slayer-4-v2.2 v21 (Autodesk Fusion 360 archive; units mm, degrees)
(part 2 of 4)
sketch "Sketch25" plane through (0, 0, 2) normal (0, 0, 1) x axis (-1, 0, 0)
  line L1 (-27.3161, -18.7368) -> (-34.6566, -7.8543)
  line L2 (-7.8768, -19.0795) -> (-13.4582, -18.707)
  line L3 (13.4582, -18.707) -> (7.8768, -19.0795)
  line L4 (7.8768, 19.0795) -> (13.4582, 18.707)
  line L5 (-13.4582, 18.707) -> (-7.8768, 19.0795)
  line L6 (-34.6566, 7.8543) -> (-27.3161, 18.7368)
  line L7 (-34.9985, -6.7359) -> (-34.9985, 6.7359)
  line L8 (-28.5272, 6) -> (-25.1483, 6)
  line L9 (-28.4467, 11.6958) -> (-30.1852, 9.1184)
  line L10 (-29.9985, -3) -> (-23.1491, -3)
  line L11 (-31.9985, 1) -> (-31.9985, -1)
  line L12 (-23.1491, 3) -> (-29.9985, 3)
  line L13 (15.3479, -5.782) -> (13.4133, -8.1699)
  line L14 (19.6919, -8.9044) -> (18.7852, -6.3678)
  line L15 (13.4936, -15.6979) -> (15.3167, -15.5763)
  line L16 (13.4133, 8.1699) -> (15.3479, 5.782)
  line L17 (15.3167, 15.5763) -> (13.4936, 15.6979)
  line L18 (18.7852, 6.3678) -> (19.6919, 8.9044)
  line L19 (-15.3479, 5.782) -> (-13.4133, 8.1699)
  line L20 (-19.6919, 8.9044) -> (-18.7852, 6.3678)
  line L21 (-13.4936, 15.6979) -> (-15.3167, 15.5763)
  line L22 (-13.4133, -8.1699) -> (-15.3479, -5.782)
  line L23 (-15.3167, -15.5763) -> (-13.4936, -15.6979)
  line L24 (-18.7852, -6.3678) -> (-19.6919, -8.9044)
  line L25 (-30.1852, -9.1184) -> (-28.4467, -11.6958)
  line L26 (-25.1483, -6) -> (-28.5272, -6)
  line L27 (42, 0) -> (-35, 0)
  line L28 (42, -18.878) -> (42, 0)
  line L29 (-35, 0) -> (-35, -20)
  line L30 (0.0223, -24.9973) -> (-35, -20)
  line L31 (42, -18.878) -> (0.0223, -24.9973)
  arc A1 centre (-32.9985, -6.7359) radius 2 clockwise from (-34.6566, -7.8543) to (-34.9985, -6.7359)
  arc A2 centre (-24, -16.5) radius 4 clockwise from (-22.465, -20.1938) to (-27.3161, -18.7368)
  arc A3 centre (-14.7902, -38.6626) radius 20 clockwise from (-22.465, -20.1938) to (-13.4582, -18.707)
  arc A4 centre (-9.0756, -37.0396) radius 18 clockwise from (-7.8768, -19.0795) to (-1.2965, -20.8073)
  arc A5 centre (0, -18.1019) radius 3 clockwise from (1.2965, -20.8073) to (-1.2965, -20.8073)
  arc A6 centre (9.0756, -37.0396) radius 18 clockwise from (1.2965, -20.8073) to (7.8768, -19.0795)
  arc A7 centre (14.7902, -38.6626) radius 20 clockwise from (13.4582, -18.707) to (22.465, -20.1938)
  arc A8 centre (24, -16.5) radius 4 clockwise from (26.8498, -13.6931) to (22.465, -20.1938)
  arc A9 centre (41.099, 0.3411) radius 20 clockwise from (26.8498, -13.6931) to (21.1019, 0)
  arc A10 centre (41.099, -0.3411) radius 20 clockwise from (21.1019, 0) to (26.8498, 13.6931)
  arc A11 centre (24, 16.5) radius 4 clockwise from (22.465, 20.1938) to (26.8498, 13.6931)
  arc A12 centre (14.7902, 38.6626) radius 20 clockwise from (22.465, 20.1938) to (13.4582, 18.707)
  arc A13 centre (9.0756, 37.0396) radius 18 clockwise from (7.8768, 19.0795) to (1.2965, 20.8073)
  arc A14 centre (0, 18.1019) radius 3 clockwise from (-1.2965, 20.8073) to (1.2965, 20.8073)
  arc A15 centre (-9.0756, 37.0396) radius 18 clockwise from (-1.2965, 20.8073) to (-7.8768, 19.0795)
  arc A16 centre (-14.7902, 38.6626) radius 20 clockwise from (-13.4582, 18.707) to (-22.465, 20.1938)
  arc A17 centre (-24, 16.5) radius 4 clockwise from (-27.3161, 18.7368) to (-22.465, 20.1938)
  arc A18 centre (-32.9985, 6.7359) radius 2 clockwise from (-34.9985, 6.7359) to (-34.6566, 7.8543)
  arc A19 centre (-28.5272, 8) radius 2 clockwise from (-28.5272, 6) to (-30.1852, 9.1184)
  arc A20 centre (-26.7887, 10.5774) radius 2 clockwise from (-28.4467, 11.6958) to (-25.1986, 11.7906)
  arc A21 centre (-41.099, -0.3411) radius 20 clockwise from (-25.1986, 11.7906) to (-23.376, 8.9268)
  arc A22 centre (-25.1483, 8) radius 2 clockwise from (-23.376, 8.9268) to (-25.1483, 6)
  arc A23 centre (-41.099, -0.3411) radius 20 clockwise from (-21.1546, 1.149) to (-21.1019, 0)
  arc A24 centre (-41.099, 0.3411) radius 20 clockwise from (-21.1019, 0) to (-21.1546, -1.149)
  arc A25 centre (-23.1491, -1) radius 2 clockwise from (-21.1546, -1.149) to (-23.1491, -3)
  arc A26 centre (-29.9985, -1) radius 2 clockwise from (-29.9985, -3) to (-31.9985, -1)
  arc A27 centre (-29.9985, 1) radius 2 clockwise from (-31.9985, 1) to (-29.9985, 3)
  arc A28 centre (-23.1491, 1) radius 2 clockwise from (-23.1491, 3) to (-21.1546, 1.149)
  circle C1 centre (18.1019, 0) radius 1.05
  circle C2 centre (10, -10) radius 1.05
  circle C3 centre (24, -16.5) radius 1.55
  arc A29 centre (16.9019, -7.041) radius 2 clockwise from (15.3479, -5.782) to (18.7852, -6.3678)
  arc A30 centre (14.9837, -10.5874) radius 5 clockwise from (19.6919, -8.9044) to (15.3167, -15.5763)
  arc A31 centre (13.3604, -13.7024) radius 2 clockwise from (13.4936, -15.6979) to (12.0163, -12.2214)
  arc A32 centre (10, -10) radius 3 clockwise from (12.9804, -9.6573) to (12.0163, -12.2214)
  arc A33 centre (14.9673, -9.4289) radius 2 clockwise from (12.9804, -9.6573) to (13.4133, -8.1699)
  arc A34 centre (14.9673, 9.4289) radius 2 clockwise from (13.4133, 8.1699) to (12.9804, 9.6573)
  arc A35 centre (10, 10) radius 3 clockwise from (12.0163, 12.2214) to (12.9804, 9.6573)
  arc A36 centre (13.3604, 13.7024) radius 2 clockwise from (12.0163, 12.2214) to (13.4936, 15.6979)
  arc A37 centre (14.9837, 10.5874) radius 5 clockwise from (15.3167, 15.5763) to (19.6919, 8.9044)
  arc A38 centre (16.9019, 7.041) radius 2 clockwise from (18.7852, 6.3678) to (15.3479, 5.782)
  circle C4 centre (24, 16.5) radius 1.55
  circle C5 centre (10, 10) radius 1.05
  circle C6 centre (-10, 10) radius 1.05
  circle C7 centre (-24, 16.5) radius 1.55
  arc A39 centre (-16.9019, 7.041) radius 2 clockwise from (-15.3479, 5.782) to (-18.7852, 6.3678)
  arc A40 centre (-14.9837, 10.5874) radius 5 clockwise from (-19.6919, 8.9044) to (-15.3167, 15.5763)
  arc A41 centre (-13.3604, 13.7024) radius 2 clockwise from (-13.4936, 15.6979) to (-12.0163, 12.2214)
  arc A42 centre (-10, 10) radius 3 clockwise from (-12.9804, 9.6573) to (-12.0163, 12.2214)
  arc A43 centre (-14.9673, 9.4289) radius 2 clockwise from (-12.9804, 9.6573) to (-13.4133, 8.1699)
  arc A44 centre (-14.9673, -9.4289) radius 2 clockwise from (-13.4133, -8.1699) to (-12.9804, -9.6573)
  arc A45 centre (-10, -10) radius 3 clockwise from (-12.0163, -12.2214) to (-12.9804, -9.6573)
  arc A46 centre (-13.3604, -13.7024) radius 2 clockwise from (-12.0163, -12.2214) to (-13.4936, -15.6979)
  arc A47 centre (-14.9837, -10.5874) radius 5 clockwise from (-15.3167, -15.5763) to (-19.6919, -8.9044)
  arc A48 centre (-16.9019, -7.041) radius 2 clockwise from (-18.7852, -6.3678) to (-15.3479, -5.782)
  circle C8 centre (-24, -16.5) radius 1.55
  circle C9 centre (-10, -10) radius 1.05
  circle C10 centre (-18.1019, 0) radius 1.05
  circle C11 centre (0, -18.1019) radius 1.05
  circle C12 centre (0, 18.1019) radius 1.05
  arc A49 centre (0, 3.3668) radius 9 clockwise from (-7.5, 8.3417) to (7.5, 8.3417)
  arc A50 centre (10, 10) radius 3 clockwise from (8.3417, 7.5) to (7.5, 8.3417)
  arc A51 centre (3.3668, 0) radius 9 clockwise from (8.3417, 7.5) to (8.3417, -7.5)
  arc A52 centre (10, -10) radius 3 clockwise from (7.5, -8.3417) to (8.3417, -7.5)
  arc A53 centre (0, -3.3668) radius 9 clockwise from (7.5, -8.3417) to (-7.5, -8.3417)
  arc A54 centre (-10, -10) radius 3 clockwise from (-8.3417, -7.5) to (-7.5, -8.3417)
  arc A55 centre (-3.3668, 0) radius 9 clockwise from (-8.3417, -7.5) to (-8.3417, 7.5)
  arc A56 centre (-10, 10) radius 3 clockwise from (-7.5, 8.3417) to (-8.3417, 7.5)
  arc A57 centre (-26.7887, -10.5774) radius 2 clockwise from (-25.1986, -11.7906) to (-28.4467, -11.6958)
  arc A58 centre (-28.5272, -8) radius 2 clockwise from (-30.1852, -9.1184) to (-28.5272, -6)
  arc A59 centre (-25.1483, -8) radius 2 clockwise from (-25.1483, -6) to (-23.376, -8.9268)
  arc A60 centre (-41.099, 0.3411) radius 20 clockwise from (-23.376, -8.9268) to (-25.1986, -11.7906)
  horizontal L27
  vertical L28
  vertical L29
extrude "Extrude26" new body sketch "Sketch25" profile of A1 L1 A2 A3 L2 A4 A5 A6 L3 A7 A8 A9 L7 A24 A25 L10 A26 L11 C1 C2 C3 L13 A29 L14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 along normal blind 43
sketch "Sketch33" plane through (0, 0, 0) normal (0, -1, 0) x axis (1, 0, 0)
  line L1 (35, 2) -> (-42, 2)
  line L2 (35, 45) -> (35, 2)
  line L3 (-42, 45) -> (35, 45)
  line L4 (-42, 2) -> (-42, 45)
  line L5 (35, 27.2231) -> (-42, 45)
  point P5 (-42, 45)
  point P6 (-42, 45)
  point P7 (35, 27.2231)
  coincident P5 P6
  coincident L2 P7
  dimension "d678" angle L3 L5 = 13
extrude "Extrude45" cut sketch "Sketch33" profile of L2 L3 L5 against normal blind 29
chamfer "Chamfer4" distance 12 Rotate Angle 35
chamfer "Chamfer5" distance 15 Rotate Angle 30
work_plane "WorkPlane14" RotateAngle 77 (= "90 deg - 13 deg")
sketch "Sketch50" plane through (-49.738, 0, 11.4829) normal (-0.9744, 0, 0.225) x axis (0, -1, 0)
  line L1 (0, 34.3987) -> (-9.322, 34.3987)
  line L2 (-38.1198, 34.3987) -> (0, 34.3987)
  line L3 (-38.1198, 9.6434) -> (-38.1198, 34.3987)
  line L4 (-38.1198, 9.6434) -> (0, 34.3987)
  point P3 (0, 34.3987)
  point P4 (0, 34.3987)
  point P7 (0, 34.3987)
  coincident P3 P4
  parallel L1 L2
  perpendicular L1 L3
  coincident P3 P7
  dimension "d680" angle L2 L4 = 33
extrude "Extrude72" cut sketch "Sketch50" against normal blind 97
sketch "Sketch26" plane through (0, 0, 0) normal (0, -1, 0) x axis (1, 0, 0)
  line L1 (-42, 2) -> (-42, 45)
  line L2 (35, 2) -> (-42, 2)
  line L3 (35, 27.2231) -> (35, 2)
  line L4 (-19, 2) -> (-19, 35)
  line L5 (-42, 45) -> (35, 27.2231)
  line L6 (35, 27.2231) -> (45.0403, 62.0037)
  curve K1 (-19, 35) -> (45.0403, 62.0037)
  curve K2 (40, 64) -> (50.0806, 60.0075)
  curve K3 (-24, 35) -> (-14, 35)
  line L7 (-42, 35) -> (-19, 35)
  point P6 (-19, 2)
  point P5 (35, 27.2231)
  point P7 (35, 27.2231)
  point P10 (45.0403, 62.0037)
  point P15 (-19, 35)
  point P16 (-42, 35)
  coincident L2 P6
  perpendicular L2 L4
  coincident P5 P7
  midpoint P10 K2
  midpoint K3 P15
  coincident L1 P16
  perpendicular L1 L7
  dimension "d688" distance P6 P15 = 33
extrude "Extrude73" cut sketch "Sketch26" profile of L1 L5 K1 L7 against normal blind 69
extrude "Extrude27" add sketch "Sketch26" profile of L2 L3 L4 L5 L6 K1 against normal blind 2.5
move "Move3"
split "Split1" bodies "cam-mount-shell (1)"
extrude "Extrude36" cut of existing geometry blind -17
sketch "Sketch30" plane through (0, 0, 0) normal (0, -1, 0) x axis (1, 0, 0)
  line L1 (-42, 2) -> (-42, 35)
  line L2 (35, 2) -> (-42, 2)
  line L3 (35, 27.2231) -> (35, 2)
  line L4 (-5.4047, 68.0196) -> (-42, 2)
  line L5 (45.0403, 62.0037) -> (35, 27.2231)
  line L6 (-42, 35) -> (-19, 35)
  curve K1 (-9.0663, 37.3967) -> (45.0403, 62.0037)
  curve K2 (-19, 35) -> (-9.0663, 37.3967)
  point P3 (-42, 2)
  point P6 (-42, 2)
  coincident P3 P6
  dimension "d687" angle L1 L4 = 29
extrude "Extrude37" cut sketch "Sketch30" profile of L1 L4 against normal blind 24
sketch "Sketch31" plane through (-35.0636, 0, 35.0636) normal (-0.7071, 0, 0.7071) x axis (0, -1, 0)
  line L1 (0, -1.4655) -> (0, -3.038)
  line L2 (0, -17.038) -> (0, -18.6105)
  line L3 (0, -19.238) -> (0, -0.838)
  circle C1 centre (0, -10.038) radius 9.2
  circle C2 centre (0, -10.038) radius 7.2
  point P7 (0, -0.838)
  point P8 (0, -19.238)
  coincident C1 P7
  coincident C1 P8
  parallel L2 L3
  concentric C1 C2
  dimension "d424" diameter C2 = 14.4
loft "Loft6" sketch "Sketch31"
shell "Shell5" innerThickness 1.4
extrude "Extrude39" cut of existing geometry blind -3
component_insert "Component Insert1"
extrude "Extrude40" cut sketch "Sketch31" profile of L3 C2 against normal blind 6
extrude "Extrude44" add of existing geometry blind -6
chamfer "Chamfer6" distance 2 Rotate Angle 45
component_insert "Component Insert2"
position "Position2"
component_insert "Component Insert3"
position "Position3"
component_insert "Component Insert4"
position "Position4"
component_insert "Component Insert5"
position "Position5"
sketch "Sketch34" plane through (0, 0, 2) normal (0, 0, -1) x axis (1, 0, 0)
  line L1 (-42, -9.322) -> (-42, 0)
  line L2 (25.6648, -21.332) -> (-0.0223, -24.9973)
  line L3 (35, -8) -> (25.6648, -21.332)
  line L4 (35, 0) -> (35, -8)
  line L5 (-40.5206, 0) -> (-40.5206, -1.4)
  line L6 (33.6, -7.5586) -> (33.6, 0)
  line L7 (24.8662, -20.0318) -> (33.6, -7.5586)
  line L8 (-0.0202, -23.5828) -> (24.8662, -20.0318)
  curve K1 (-40.5206, -1.4) -> (-40.5365, -8.6938)
  line L9 (2.5, 0) -> (20, 0)
  line L10 (-32.4922, -15.0454) -> (-33.3597, -16.1441)
  line L11 (-42, 0) -> (-40.5206, 0)
  line L12 (33.6, 0) -> (35, 0)
  line L13 (-27.1569, -21.0418) -> (-42, -9.322)
  line L14 (-0.0223, -24.9973) -> (-27.1569, -21.0418)
  line L15 (-26.5837, -19.7105) -> (-0.0202, -23.5828)
  line L16 (-40.5365, -8.6938) -> (-26.5837, -19.7105)
  point P19 (-33.3597, -16.1441)
  point P20 (-32.4922, -15.0454)
  coincident P19 L13
  perpendicular L10 L13
  coincident P20 L16
sketch "Sketch35" plane through (0, 0, -7) normal (0, 0, -1) x axis (1, 0, 0)
  line L1 (-40.0019, -3.8052) -> (-40.0019, 3.8052)
  line L2 (-29.4521, -15.7011) -> (-38.3863, -7.4856)
  line L3 (-10.5232, -16.1251) -> (-13.4179, -16.642)
  line L4 (9.4685, -16.0316) -> (-9.4685, -16.0316)
  line L5 (13.4179, -16.642) -> (10.5232, -16.1251)
  line L6 (25.5, 4.935) -> (25.5, -4.935)
  line L7 (10.5232, 16.1251) -> (13.4179, 16.642)
  line L8 (-9.4685, 16.0316) -> (9.4685, 16.0316)
  line L9 (-13.4179, 16.642) -> (-10.5232, 16.1251)
  line L10 (-38.3863, 7.4856) -> (-29.4521, 15.7011)
  line L11 (-27.7146, -6) -> (-30.4401, -6)
  line L12 (-31.7938, -9.4722) -> (-29.4762, -11.6034)
  line L13 (-37.0019, 1) -> (-37.0019, -1)
  line L14 (-27.5, 3) -> (-35.0019, 3)
  line L15 (-25.5, -1) -> (-25.5, 1)
  line L16 (-35.0019, -3) -> (-27.5, -3)
  line L17 (-30.4401, 6) -> (-27.7146, 6)
  line L18 (-29.4762, 11.6034) -> (-31.7938, 9.4722)
  line L19 (22.5, -4.3626) -> (22.5, 4.3626)
  curve K1 (22.5, -4.3626) -> (18.1183, -6.0086)
  curve K2 (15, 0) -> (18.1183, -6.0086)
  curve K3 (15, 0) -> (18.1183, 6.0086)
  curve K4 (22.5, 4.3626) -> (18.1183, 6.0086)
  line L20 (-5.0161, -4) -> (-8.4244, -4)
  line L21 (-1.1704, -9.0423) -> (-3.2434, -5.074)
  line L22 (-10, -11.9684) -> (-2.9431, -11.9684)
  curve K5 (-12.1729, -8.1647) -> (-10, -11.9684)
  curve K6 (-12.1729, -8.1647) -> (-10.6866, -5.436)
  curve K7 (-8.4244, -4) -> (-10.6866, -5.436)
  line L23 (4.9544, -11.9684) -> (10, -11.9684)
  line L24 (1.1087, -6.926) -> (3.1817, -10.8944)
  line L25 (8.4244, -4) -> (2.8814, -4)
  curve K8 (8.4244, -4) -> (10.6866, -5.436)
  curve K9 (12.1729, -8.1647) -> (10.6866, -5.436)
  curve K10 (12.1729, -8.1647) -> (10, -11.9684)
  line L26 (10, 11.9684) -> (4.9544, 11.9684)
  curve K11 (12.1729, 8.1647) -> (10, 11.9684)
  curve K12 (12.1729, 8.1647) -> (10.6866, 5.436)
  curve K13 (8.4244, 4) -> (10.6866, 5.436)
  line L27 (2.8814, 4) -> (8.4244, 4)
  line L28 (3.1817, 10.8944) -> (1.1087, 6.926)
  curve K14 (-15, 0) -> (-18.1183, -6.0086)
  curve K15 (-22.5, -4.3626) -> (-18.1183, -6.0086)
  line L29 (-22.5, 4.3626) -> (-22.5, -4.3626)
  curve K16 (-22.5, 4.3626) -> (-18.1183, 6.0086)
  curve K17 (-15, 0) -> (-18.1183, 6.0086)
  line L30 (-8.4244, 4) -> (-5.0161, 4)
  curve K18 (-8.4244, 4) -> (-10.6866, 5.436)
  curve K19 (-12.1729, 8.1647) -> (-10.6866, 5.436)
  curve K20 (-12.1729, 8.1647) -> (-10, 11.9684)
  line L31 (-2.9431, 11.9684) -> (-10, 11.9684)
  line L32 (-3.2434, 5.074) -> (-1.1704, 9.0423)
  line L33 (-89, 0) -> (0, 0)
  line L34 (-41.4019, -6.6146) -> (-33.1399, -14.2119)
  line L35 (-33.1399, -14.2119) -> (-32.1923, -13.1813)
  line L36 (-41.4019, -6.6146) -> (-41.4019, 0)
  line L37 (-40.0019, 0) -> (-41.4019, 0)
  arc A1 centre (-35.0019, 3.8052) radius 5 clockwise from (-40.0019, 3.8052) to (-38.3863, 7.4856)
  arc A2 centre (-35.0019, -3.8052) radius 5 clockwise from (-38.3863, -7.4856) to (-40.0019, -3.8052)
  arc A3 centre (-34.8671, -21.5899) radius 8 clockwise from (-29.4521, -15.7011) to (-27.6224, -18.1966)
  arc A4 centre (-24, -16.5) radius 4 clockwise from (-21.8856, -19.8955) to (-27.6224, -18.1966)
  arc A5 centre (-9.199, -40.2682) radius 24 clockwise from (-21.8856, -19.8955) to (-13.4179, -16.642)
  arc A6 centre (-9.4685, -22.0316) radius 6 clockwise from (-10.5232, -16.1251) to (-9.4685, -16.0316)
  arc A7 centre (9.4685, -22.0316) radius 6 clockwise from (9.4685, -16.0316) to (10.5232, -16.1251)
  arc A8 centre (9.199, -40.2682) radius 24 clockwise from (13.4179, -16.642) to (21.8856, -19.8955)
  arc A9 centre (24, -16.5) radius 4 clockwise from (27.6429, -14.8479) to (21.8856, -19.8955)
  arc A10 centre (49.5, -4.935) radius 24 clockwise from (27.6429, -14.8479) to (25.5, -4.935)
  arc A11 centre (49.5, 4.935) radius 24 clockwise from (25.5, 4.935) to (27.6429, 14.8479)
  arc A12 centre (24, 16.5) radius 4 clockwise from (21.8856, 19.8955) to (27.6429, 14.8479)
  arc A13 centre (9.199, 40.2682) radius 24 clockwise from (21.8856, 19.8955) to (13.4179, 16.642)
  arc A14 centre (9.4685, 22.0316) radius 6 clockwise from (10.5232, 16.1251) to (9.4685, 16.0316)
  arc A15 centre (-9.4685, 22.0316) radius 6 clockwise from (-9.4685, 16.0316) to (-10.5232, 16.1251)
  arc A16 centre (-9.199, 40.2682) radius 24 clockwise from (-13.4179, 16.642) to (-21.8856, 19.8955)
  arc A17 centre (-24, 16.5) radius 4 clockwise from (-27.6224, 18.1966) to (-21.8856, 19.8955)
  arc A18 centre (-34.8671, 21.5899) radius 8 clockwise from (-27.6224, 18.1966) to (-29.4521, 15.7011)
  arc A19 centre (-30.4401, -8) radius 2 clockwise from (-31.7938, -9.4722) to (-30.4401, -6)
  arc A20 centre (-27.7146, -8) radius 2 clockwise from (-27.7146, -6) to (-25.7341, -8.2786)
  arc A21 centre (-49.5, -4.935) radius 24 clockwise from (-25.7341, -8.2786) to (-26.179, -10.6035)
  arc A22 centre (-28.1225, -10.1312) radius 2 clockwise from (-26.179, -10.6035) to (-29.4762, -11.6034)
  arc A23 centre (-35.0019, 1) radius 2 clockwise from (-37.0019, 1) to (-35.0019, 3)
  arc A24 centre (-27.5, 1) radius 2 clockwise from (-27.5, 3) to (-25.5, 1)
  arc A25 centre (-27.5, -1) radius 2 clockwise from (-25.5, -1) to (-27.5, -3)
  arc A26 centre (-35.0019, -1) radius 2 clockwise from (-35.0019, -3) to (-37.0019, -1)
  arc A27 centre (-30.4401, 8) radius 2 clockwise from (-30.4401, 6) to (-31.7938, 9.4722)
  arc A28 centre (-28.1225, 10.1312) radius 2 clockwise from (-29.4762, 11.6034) to (-26.179, 10.6035)
  arc A29 centre (-49.5, 4.935) radius 24 clockwise from (-26.179, 10.6035) to (-25.7341, 8.2786)
  arc A30 centre (-27.7146, 8) radius 2 clockwise from (-25.7341, 8.2786) to (-27.7146, 6)
  arc A31 centre (-5.0161, -6) radius 2 clockwise from (-5.0161, -4) to (-3.2434, -5.074)
  arc A32 centre (-2.9431, -9.9684) radius 2 clockwise from (-1.1704, -9.0423) to (-2.9431, -11.9684)
  circle C1 centre (-24, -16.5) radius 1.55
  circle C2 centre (24, -16.5) radius 1.55
  arc A33 centre (4.9544, -9.9684) radius 2 clockwise from (4.9544, -11.9684) to (3.1817, -10.8944)
  arc A34 centre (2.8814, -6) radius 2 clockwise from (1.1087, -6.926) to (2.8814, -4)
  arc A35 centre (2.8814, 6) radius 2 clockwise from (2.8814, 4) to (1.1087, 6.926)
  arc A36 centre (4.9544, 9.9684) radius 2 clockwise from (3.1817, 10.8944) to (4.9544, 11.9684)
  circle C3 centre (24, 16.5) radius 1.55
  circle C4 centre (-24, 16.5) radius 1.55
  arc A37 centre (-2.9431, 9.9684) radius 2 clockwise from (-2.9431, 11.9684) to (-1.1704, 9.0423)
  arc A38 centre (-5.0161, 6) radius 2 clockwise from (-3.2434, 5.074) to (-5.0161, 4)
  point P1 (0, 0)
  point P130 (0, 0)
  point P132 (-41.4019, 0)
  point P136 (-41.4019, 0)
  point P137 (-40.0019, 0)
  point P135 (-32.1923, -13.1813)
  coincident P1 P130
  horizontal L33
  coincident L33 P132
  symmetric L33 P132 P136
  midpoint L1 P137
  parallel L2 L34
  coincident L2 P135
  perpendicular L2 L35
  dimension "d791" distance L1 L36 = 1.4
  dimension "d792" distance L2 L34 = 1.4
loft "Loft7" sketch "Sketch34" + "Sketch35"
chamfer "Chamfer14" distance 3
sketch "Sketch36" plane through (0, 0, 2) normal (0, 0, 1) x axis (-1, 0, 0)
  line L1 (-27.3161, -18.7368) -> (-34.6566, -7.8543)
  line L2 (-7.8768, -19.0795) -> (-13.4582, -18.707)
  line L3 (13.4582, -18.707) -> (7.8768, -19.0795)
  line L4 (7.8768, 19.0795) -> (13.4582, 18.707)
  line L5 (-13.4582, 18.707) -> (-7.8768, 19.0795)
  line L6 (-34.6566, 7.8543) -> (-27.3161, 18.7368)
  line L7 (-34.9985, -6.7359) -> (-34.9985, 6.7359)
  line L8 (-28.5272, 6) -> (-25.1483, 6)
  line L9 (-28.4467, 11.6958) -> (-30.1852, 9.1184)
  line L10 (-29.9985, -3) -> (-23.1491, -3)
  line L11 (-31.9985, 1) -> (-31.9985, -1)
  line L12 (-23.1491, 3) -> (-29.9985, 3)
  line L13 (15.3479, -5.782) -> (13.4133, -8.1699)
  line L14 (19.6919, -8.9044) -> (18.7852, -6.3678)
  line L15 (13.4936, -15.6979) -> (15.3167, -15.5763)
  line L16 (13.4133, 8.1699) -> (15.3479, 5.782)
  line L17 (15.3167, 15.5763) -> (13.4936, 15.6979)
  line L18 (18.7852, 6.3678) -> (19.6919, 8.9044)
  line L19 (-15.3479, 5.782) -> (-13.4133, 8.1699)
  line L20 (-19.6919, 8.9044) -> (-18.7852, 6.3678)
  line L21 (-13.4936, 15.6979) -> (-15.3167, 15.5763)
  line L22 (-13.4133, -8.1699) -> (-15.3479, -5.782)
  line L23 (-15.3167, -15.5763) -> (-13.4936, -15.6979)
  line L24 (-18.7852, -6.3678) -> (-19.6919, -8.9044)
  line L25 (-30.1852, -9.1184) -> (-28.4467, -11.6958)
  line L26 (-25.1483, -6) -> (-28.5272, -6)
  line L27 (-2.5, 0) -> (-20, 0)
  arc A1 centre (-32.9985, -6.7359) radius 2 clockwise from (-34.6566, -7.8543) to (-34.9985, -6.7359)
  arc A2 centre (-24, -16.5) radius 4 clockwise from (-22.465, -20.1938) to (-27.3161, -18.7368)
  arc A3 centre (-14.7902, -38.6626) radius 20 clockwise from (-22.465, -20.1938) to (-13.4582, -18.707)
  arc A4 centre (-9.0756, -37.0396) radius 18 clockwise from (-7.8768, -19.0795) to (-1.2965, -20.8073)
  arc A5 centre (0, -18.1019) radius 3 clockwise from (1.2965, -20.8073) to (-1.2965, -20.8073)
  arc A6 centre (9.0756, -37.0396) radius 18 clockwise from (1.2965, -20.8073) to (7.8768, -19.0795)
  arc A7 centre (14.7902, -38.6626) radius 20 clockwise from (13.4582, -18.707) to (22.465, -20.1938)
  arc A8 centre (24, -16.5) radius 4 clockwise from (26.8498, -13.6931) to (22.465, -20.1938)
  arc A9 centre (41.099, 0.3411) radius 20 clockwise from (26.8498, -13.6931) to (21.1019, 0)
  arc A10 centre (41.099, -0.3411) radius 20 clockwise from (21.1019, 0) to (26.8498, 13.6931)
  arc A11 centre (24, 16.5) radius 4 clockwise from (22.465, 20.1938) to (26.8498, 13.6931)
  arc A12 centre (14.7902, 38.6626) radius 20 clockwise from (22.465, 20.1938) to (13.4582, 18.707)
  arc A13 centre (9.0756, 37.0396) radius 18 clockwise from (7.8768, 19.0795) to (1.2965, 20.8073)
  arc A14 centre (0, 18.1019) radius 3 clockwise from (-1.2965, 20.8073) to (1.2965, 20.8073)
  arc A15 centre (-9.0756, 37.0396) radius 18 clockwise from (-1.2965, 20.8073) to (-7.8768, 19.0795)
  arc A16 centre (-14.7902, 38.6626) radius 20 clockwise from (-13.4582, 18.707) to (-22.465, 20.1938)
  arc A17 centre (-24, 16.5) radius 4 clockwise from (-27.3161, 18.7368) to (-22.465, 20.1938)
  arc A18 centre (-32.9985, 6.7359) radius 2 clockwise from (-34.9985, 6.7359) to (-34.6566, 7.8543)
  arc A19 centre (-28.5272, 8) radius 2 clockwise from (-28.5272, 6) to (-30.1852, 9.1184)
  arc A20 centre (-26.7887, 10.5774) radius 2 clockwise from (-28.4467, 11.6958) to (-25.1986, 11.7906)
  arc A21 centre (-41.099, -0.3411) radius 20 clockwise from (-25.1986, 11.7906) to (-23.376, 8.9268)
  arc A22 centre (-25.1483, 8) radius 2 clockwise from (-23.376, 8.9268) to (-25.1483, 6)
  arc A23 centre (-41.099, -0.3411) radius 20 clockwise from (-21.1546, 1.149) to (-21.1019, 0)
  arc A24 centre (-41.099, 0.3411) radius 20 clockwise from (-21.1019, 0) to (-21.1546, -1.149)
  arc A25 centre (-23.1491, -1) radius 2 clockwise from (-21.1546, -1.149) to (-23.1491, -3)
  arc A26 centre (-29.9985, -1) radius 2 clockwise from (-29.9985, -3) to (-31.9985, -1)
  arc A27 centre (-29.9985, 1) radius 2 clockwise from (-31.9985, 1) to (-29.9985, 3)
  arc A28 centre (-23.1491, 1) radius 2 clockwise from (-23.1491, 3) to (-21.1546, 1.149)
  circle C1 centre (18.1019, 0) radius 1.05
  circle C2 centre (10, -10) radius 1.05
  circle C3 centre (24, -16.5) radius 1.55
  arc A29 centre (16.9019, -7.041) radius 2 clockwise from (15.3479, -5.782) to (18.7852, -6.3678)
  arc A30 centre (14.9837, -10.5874) radius 5 clockwise from (19.6919, -8.9044) to (15.3167, -15.5763)
  arc A31 centre (13.3604, -13.7024) radius 2 clockwise from (13.4936, -15.6979) to (12.0163, -12.2214)
  arc A32 centre (10, -10) radius 3 clockwise from (12.9804, -9.6573) to (12.0163, -12.2214)
  arc A33 centre (14.9673, -9.4289) radius 2 clockwise from (12.9804, -9.6573) to (13.4133, -8.1699)
  arc A34 centre (14.9673, 9.4289) radius 2 clockwise from (13.4133, 8.1699) to (12.9804, 9.6573)
  arc A35 centre (10, 10) radius 3 clockwise from (12.0163, 12.2214) to (12.9804, 9.6573)
  arc A36 centre (13.3604, 13.7024) radius 2 clockwise from (12.0163, 12.2214) to (13.4936, 15.6979)
  arc A37 centre (14.9837, 10.5874) radius 5 clockwise from (15.3167, 15.5763) to (19.6919, 8.9044)
  arc A38 centre (16.9019, 7.041) radius 2 clockwise from (18.7852, 6.3678) to (15.3479, 5.782)
  circle C4 centre (24, 16.5) radius 1.55
  circle C5 centre (10, 10) radius 1.05
  circle C6 centre (-10, 10) radius 1.05
  circle C7 centre (-24, 16.5) radius 1.55
  arc A39 centre (-16.9019, 7.041) radius 2 clockwise from (-15.3479, 5.782) to (-18.7852, 6.3678)
  arc A40 centre (-14.9837, 10.5874) radius 5 clockwise from (-19.6919, 8.9044) to (-15.3167, 15.5763)
  arc A41 centre (-13.3604, 13.7024) radius 2 clockwise from (-13.4936, 15.6979) to (-12.0163, 12.2214)
  arc A42 centre (-10, 10) radius 3 clockwise from (-12.9804, 9.6573) to (-12.0163, 12.2214)
  arc A43 centre (-14.9673, 9.4289) radius 2 clockwise from (-12.9804, 9.6573) to (-13.4133, 8.1699)
  arc A44 centre (-14.9673, -9.4289) radius 2 clockwise from (-13.4133, -8.1699) to (-12.9804, -9.6573)
  arc A45 centre (-10, -10) radius 3 clockwise from (-12.0163, -12.2214) to (-12.9804, -9.6573)
  arc A46 centre (-13.3604, -13.7024) radius 2 clockwise from (-12.0163, -12.2214) to (-13.4936, -15.6979)
  arc A47 centre (-14.9837, -10.5874) radius 5 clockwise from (-15.3167, -15.5763) to (-19.6919, -8.9044)
  arc A48 centre (-16.9019, -7.041) radius 2 clockwise from (-18.7852, -6.3678) to (-15.3479, -5.782)
  circle C8 centre (-24, -16.5) radius 1.55
  circle C9 centre (-10, -10) radius 1.05
  circle C10 centre (-18.1019, 0) radius 1.05
  circle C11 centre (0, -18.1019) radius 1.05
  circle C12 centre (0, 18.1019) radius 1.05
  arc A49 centre (0, 3.3668) radius 9 clockwise from (-7.5, 8.3417) to (7.5, 8.3417)
  arc A50 centre (10, 10) radius 3 clockwise from (8.3417, 7.5) to (7.5, 8.3417)
  arc A51 centre (3.3668, 0) radius 9 clockwise from (8.3417, 7.5) to (8.3417, -7.5)
  arc A52 centre (10, -10) radius 3 clockwise from (7.5, -8.3417) to (8.3417, -7.5)
  arc A53 centre (0, -3.3668) radius 9 clockwise from (7.5, -8.3417) to (-7.5, -8.3417)
  arc A54 centre (-10, -10) radius 3 clockwise from (-8.3417, -7.5) to (-7.5, -8.3417)
  arc A55 centre (-3.3668, 0) radius 9 clockwise from (-8.3417, -7.5) to (-8.3417, 7.5)
  arc A56 centre (-10, 10) radius 3 clockwise from (-7.5, 8.3417) to (-8.3417, 7.5)
  arc A57 centre (-26.7887, -10.5774) radius 2 clockwise from (-25.1986, -11.7906) to (-28.4467, -11.6958)
  arc A58 centre (-28.5272, -8) radius 2 clockwise from (-30.1852, -9.1184) to (-28.5272, -6)
  arc A59 centre (-25.1483, -8) radius 2 clockwise from (-25.1483, -6) to (-23.376, -8.9268)
  arc A60 centre (-41.099, 0.3411) radius 20 clockwise from (-23.376, -8.9268) to (-25.1986, -11.7906)
  circle C13 centre (24, -16.5) radius 3.25
  circle C14 centre (-24, -16.5) radius 3.25
  circle C15 centre (24, -16.5) radius 4.85
  circle C16 centre (-24, -16.5) radius 4.85
  concentric A8 C13
  concentric A2 C14
  concentric A8 C15
  concentric A2 C16
  dimension "d464" diameter C13 = 6.5
  dimension "d465" diameter C14 = 6.5 (= "d464")
  dimension "d466" distance C13 C15 = 1.6
  dimension "d467" distance C14 C16 = 1.6 (= "d466")
chamfer "Chamfer13" distance 5
extrude "Extrude46" new body sketch "Sketch36" profile of L1 A2 A3 A7 A8 A9 C3 C8 A57 C13 C14 C15 C16 along normal blind 40
extrude "Extrude75" cut of existing geometry blind -15
extrude "Extrude76" cut of existing geometry blind -10
combine "Combine6"
combine "Combine7"
remove_body "RemoveBody30"
remove_body "RemoveBody41"
combine "Combine8"
combine "Combine26"
extrude "Extrude48" cut sketch "Sketch36" profile of C3 C8 C13 C14 along normal blind 15
work_plane "WorkPlane5" sketch "Sketch36" AlongDistance 17
sketch "Sketch37" plane through (0, 0, 19) normal (0, 0, 1) x axis (1, 0, 0)
  line L1 (-32.4922, 15.0454) -> (-26.5837, 19.7105)
  line L2 (-33.3597, 16.1441) -> (-32.4922, 15.0454)
  line L3 (-27.1569, 21.0418) -> (-33.3597, 16.1441)
  line L4 (-0.0223, 24.9973) -> (-27.1569, 21.0418)
  line L5 (20.715, 22.0383) -> (-0.0223, 24.9973)
  line L6 (-0.0202, 23.5828) -> (19.9163, 20.7381)
  line L7 (-26.5837, 19.7105) -> (-0.0202, 23.5828)
  line L8 (35, 8) -> (28.5327, 17.2363)
  line L9 (35, 0) -> (35, 8)
  line L10 (33.6, 0) -> (35, 0)
  line L11 (33.6, 7.5586) -> (33.6, 0)
  line L12 (27.734, 15.936) -> (33.6, 7.5586)
  line L13 (19.9163, 20.7381) -> (22.3032, 19.2719)
  line L14 (24.5045, 19.7106) -> (20.715, 22.0383)
  line L15 (28.5327, 17.2363) -> (26.6357, 18.4015)
  line L16 (27.2396, 16.2398) -> (27.734, 15.936)
  circle C1 centre (-24, 16.5) radius 4.85
  circle C2 centre (-24, 16.5) radius 3.25
  circle C3 centre (24, 16.5) radius 4.85
  circle C4 centre (24, 16.5) radius 3.25
  arc A1 centre (24, 16.5) radius 3.25 clockwise from (22.3032, 19.2719) to (24.5045, 19.7106)
  arc A2 centre (24, 16.5) radius 3.25 clockwise from (26.6357, 18.4015) to (27.2396, 16.2398)
extrude "Extrude81" cut sketch "Sketch37" profile of C3 C4 A1 A2 L8 L12 L13 L14 L15 L16 along normal blind 45
extrude "Extrude50" add sketch "Sketch37" profile of C1 C2 C3 C4 against normal blind 2
extrude "Extrude51" cut sketch "Sketch37" profile of C2 C4 along normal blind 17
extrude "Extrude52" add sketch "Sketch37" profile of C2 along normal blind 5
extrude "Extrude54" cut sketch "Sketch36" profile of C3 C8 along normal blind 42
extrude "Extrude77" cut sketch "Sketch36" profile of C3 C13 along normal blind 20
extrude "Extrude78" add sketch "Sketch37" profile of C3 C4 A1 A2 L8 L12 L13 L14 L15 L16 against normal blind 17
extrude "Extrude79" add of existing geometry blind 0.8
component_insert "Component Insert6"
sketch "Sketch39" plane through (0, 0, 0) normal (0, -1, 0) x axis (1, 0, 0)
  line L1 (-32.8277, 28.8142) -> (-35.6561, 31.6426)
  line L2 (-31.4135, 30.2284) -> (-32.8277, 28.8142)
  line L3 (33.6, 2) -> (33.6, 24.9001)
  line L4 (35, 2) -> (33.6, 2)
  line L5 (35, 27.2231) -> (35, 2)
  line L6 (33.6, 21) -> (38, 21)
  line L7 (33.6, 2) -> (33.6, 21)
  line L8 (38, 2) -> (33.6, 2)
  line L9 (38, 21) -> (38, 2)
  line L10 (-34.2636, 33.0785) -> (-31.4135, 30.2284)
  line L11 (-35.6561, 31.6426) -> (-35.6561, 34.471)
  curve K1 (-23.676, 33.6) -> (-34.2636, 33.0785)
  line L12 (-19, 33.6) -> (-23.676, 33.6)
  curve K2 (-10.8513, 35.1624) -> (-19, 33.6)
  line L13 (45.0403, 62.0037) -> (35, 27.2231)
  curve K3 (-9.0663, 37.3967) -> (45.0403, 62.0037)
  line L14 (-23.7078, 35) -> (-19, 35)
  line L15 (-35.6561, 34.471) -> (-23.7078, 35)
  line L16 (33.6, 24.9001) -> (-10.8513, 35.1624)
  curve K4 (-19, 35) -> (-9.0663, 37.3967)
  point P7 (33.6, 2)
  point P12 (33.6, 2)
  horizontal L6
  vertical L7
  horizontal L8
  vertical L9
  coincident P7 P12
extrude "Extrude56" cut sketch "Sketch39" profile of L3 L4 L5 L6 L7 L8 L9 against normal blind 19
sketch "Sketch40" plane through (0, 0, 0) normal (0, -1, 0) x axis (1, 0, 0)
  line L1 (35, 21) -> (33.6, 21)
  line L2 (-32.8277, 28.8142) -> (-35.6561, 31.6426)
  line L3 (-31.4135, 30.2284) -> (-32.8277, 28.8142)
  line L4 (-34.2636, 33.0785) -> (-31.4135, 30.2284)
  line L5 (-35.6561, 31.6426) -> (-35.6561, 34.471)
  line L6 (35, 27.2231) -> (35, 21)
  line L7 (45.0403, 62.0037) -> (35, 27.2231)
  curve K1 (-9.0663, 37.3967) -> (45.0403, 62.0037)
  line L8 (-23.7078, 35) -> (-19, 35)
  line L9 (-35.6561, 34.471) -> (-23.7078, 35)
  curve K2 (-23.676, 33.6) -> (-34.2636, 33.0785)
  line L10 (-19, 33.6) -> (-23.676, 33.6)
  curve K3 (-10.8513, 35.1624) -> (-19, 33.6)
  line L11 (33.6, 21) -> (33.6, 24.9001)
  curve K4 (-19, 35) -> (-9.0663, 37.3967)
  line L12 (33.6, 24.9001) -> (-10.8513, 35.1624)
sketch "Sketch52" plane through (0, 0, 17) normal (0, 0, -1) x axis (1, 0, 0)
  line L1 (-26.5837, -19.7105) -> (-28.5609, -18.1494)
  line L2 (-21.2417, -20.4893) -> (-26.5837, -19.7105)
  line L3 (-32.4922, -15.0454) -> (-26.5837, -19.7105)
  line L4 (-31.301, -12.8006) -> (-31.4534, -12.6802)
  line L5 (-25.6436, -17.2675) -> (-31.301, -12.8006)
  line L6 (-26.5837, -19.7105) -> (-0.0202, -23.5828)
  line L7 (-13.7578, -19.0538) -> (-22.6801, -17.7532)
  circle C1 centre (-24, -16.5) radius 3.25
  arc A1 centre (-24, -16.5) radius 4.85 clockwise from (-28.5609, -18.1494) to (-21.2417, -20.4893)
  parallel L3 L4
  parallel L3 L5
  parallel L6 L7
  dimension "d888" distance L3 L5 = 2.5
  dimension "d889" distance L6 L7 = 2.5 (= "d888")
extrude "Extrude84" add sketch "Sketch52" profile of C1 L1 L2 A1 L3 L5 L6 L7 along normal blind 15
sketch "Sketch53" plane through (0, 0, 12) normal (0, 0, -1) x axis (1, 0, 0)
  line L1 (27.734, -15.936) -> (27.2396, -16.2398)
  line L2 (28.5378, -14.7881) -> (27.734, -15.936)
  line L3 (22.3032, -19.2719) -> (20.8342, -20.1743)
  line L4 (22.3032, -19.2719) -> (19.9163, -20.7381)
  line L5 (27.734, -15.936) -> (28.5378, -14.7881)
  line L6 (27.7731, -12.3934) -> (27.7731, -12.1971)
  line L7 (25.5113, -15.6235) -> (27.7731, -12.3934)
  line L8 (17.4862, -19.2968) -> (21.8405, -16.6222)
  arc A1 centre (24, -16.5) radius 3.25 clockwise from (22.3032, -19.2719) to (27.2396, -16.2398)
  arc A2 centre (24, -16.5) radius 4.85 clockwise from (20.8342, -20.1743) to (28.5378, -14.7881)
  vertical L6
  parallel L5 L7
  parallel L3 L8
  dimension "d892" distance L5 L7 = 2
  dimension "d893" distance L4 L8 = 2.5
extrude "Extrude85" add sketch "Sketch53" profile of A1 L1 L2 A2 L3 L4 L5 L7 L8 along normal blind 10
work_plane "WorkPlane6" RotateAngle 60
work_plane "WorkPlane7" AlongDistance 74
sketch "Sketch41" plane through (64.0859, 0, 37) normal (0.866, 0, 0.5) x axis (0, 1, 0)
  line L1 (0, -20) -> (0, 39.1526)
  line L2 (0, 39.1526) -> (0, 31.1767)
  circle C1 centre (0, 19) radius 3
  circle C2 centre (0, 19) radius 5
  point P2 (0, 19)
  point P4 (0, 39.1526)
  point P7 (0, 39.1526)
  coincident P2 L2
  concentric C1 C2
  coincident P4 P7
  parallel L1 L2
  dimension "d528" diameter C1 = 6
  dimension "d529" distance C1 C2 = 2
extrude "Extrude57" new body sketch "Sketch41" profile of L2 C1 C2 along a picked direction blind -75
combine "Combine9"
extrude "Extrude58" new body sketch "Sketch41" profile of L2 C1 C2 along a picked direction blind -83
combine "Combine10"
remove_body "RemoveBody31"
combine "Combine11" bodies "canopy (1)"
remove_body "RemoveBody33"
copy_paste_bodies "CopyPasteBodies4"
sketch "Sketch42" plane through (4.3331, 0, 41.6617) normal (0, -1, 0) x axis (1, 0, 0)
  line L1 (-57, -2) -> (27, -2)
  line L2 (-57, -40) -> (-57, -2)
  line L3 (27, -40) -> (-57, -40)
  line L4 (27, -2) -> (27, -40)
  horizontal L1
  vertical L2
  horizontal L3
  vertical L4
extrude "Extrude60" sketch "Sketch40" + "Sketch42" blind -13
combine "Combine13"
remove_body "RemoveBody42"
combine "Combine12"
work_plane "WorkPlane8" AlongDistance 50
sketch "Sketch43" plane through (0, 0, 50) normal (0, 0, 1) x axis (1, 0, 0)
  line L1 (-10, 8) -> (10, 8)
  line L2 (-10, 11) -> (-10, 8)
  line L3 (10, 11) -> (-10, 11)
  line L4 (-8, 11) -> (-8, 8)
  line L5 (16.9983, 9.3299) -> (16.9983, 6.3299)
  line L6 (18.9983, 6.3299) -> (18.9983, 9.3299)
  line L7 (-5.2116, 8) -> (-18.8897, 8)
  line L8 (-23.64, 0) -> (-29.64, 0)
  line L9 (-23.64, 7) -> (-23.64, 0)
  line L10 (-29.64, 0) -> (-29.64, 5)
  line L11 (-23.64, 7) -> (-29.64, 5)
  line L12 (16.9983, 6.3299) -> (18.9983, 6.3299)
  line L13 (16.9983, 9.3299) -> (18.9983, 9.3299)
  line L14 (10, 11) -> (10, 8)
  line L15 (55, 0) -> (-70, 0)
  circle C1 centre (0, 11) radius 3.5
  circle C2 centre (10.9983, 9.5) radius 3
  point P6 (-8, 8)
  point P7 (-8, 11)
  point P12 (-18.8897, 8)
  point P18 (0, 11)
  point P15 (-23.64, 0)
  point P2 (10, 8)
  point P3 (-10, 8)
  point P5 (10, 11)
  point P8 (18.9983, 6.3299)
  point P11 (18.9983, 9.3299)
  point P16 (-23.64, 7)
  point P19 (10.9983, 9.5)
  point P14 (-29.64, 0)
  point P17 (-29.64, 5)
  horizontal L1
  vertical L2
  horizontal L3
  coincident L1 P6
  coincident L3 P7
  perpendicular L3 L4
  vertical L6
  horizontal L7
  coincident L1 P12
  horizontal L8
  midpoint L3 P18
  vertical L10
  perpendicular L6 L12
  perpendicular L5 L13
  perpendicular L3 L14
  horizontal L15
  coincident P15 L15
  dimension "d545" distance P2 P3 = 20
  dimension "d546" distance P2 P5 = 3
  dimension "d548" distance L2 L4 = 2 (= "d547")
  dimension "d565" distance P8 P11 = 3
  dimension "d566" distance L5 L6 = 2
  dimension "d637" distance L9 L10 = 6
  dimension "d638" diameter C1 = 7
  dimension "d639" diameter C2 = 6
  dimension "d640" distance P15 P16 = 7
  dimension "d677" distance L5 P19 = 6
  dimension "d756" distance P14 P17 = 5
extrude "Extrude61" cut sketch "Sketch43" profile of L1 L2 L3 L4 L5 L6 L8 L9 L10 C1 C2 L11 L12 L13 L14 against normal blind 33
sketch "Sketch51" plane through (0, 0, 0) normal (0, -1, 0) x axis (1, 0, 0)
  line L1 (-19, 33.6) -> (-23.64, 33.6)
  curve K1 (-10.8513, 35.1624) -> (-19, 33.6)
  line L2 (45.0403, 62.0037) -> (41.3696, 49.2882)
  curve K2 (-9.0663, 37.3967) -> (45.0403, 62.0037)
  line L3 (-23.64, 35) -> (-19, 35)
  line L4 (-12.5299, 35) -> (-23.64, 35)
  line L5 (-12.5299, 27.0748) -> (-12.5299, 35)
  line L6 (-23.64, 27.0748) -> (-12.5299, 27.0748)
  line L7 (-23.64, 35) -> (-23.64, 27.0748)
  line L8 (8.9751, 30.5852) -> (-10.8513, 35.1624)
  curve K3 (-19, 35) -> (-9.0663, 37.3967)
  line L9 (-23.64, 33.6) -> (-23.64, 35)
  line L10 (41.3696, 49.2882) -> (8.9751, 30.5852)
  point P2 (-23.64, 35)
  point P11 (-23.64, 35)
  horizontal L4
  vertical L5
  horizontal L6
  vertical L7
  coincident P2 P11
extrude "Extrude67" new body sketch "Sketch51" profile of L1 K1 L5 L6 L7 against normal blind 24
copy_paste_bodies "CopyPasteBodies3"
combine "Combine22"
combine "Combine23"
remove_body "RemoveBody24"
combine "Combine24"
combine "Combine25"
work_plane "WorkPlane12" AlongDistance 10.5
sketch "Sketch46" plane through (0, 10.5, 0) normal (0, 1, 0) x axis (1, 0, 0)
  circle C1 centre (-31.43, -16.9) radius 1
  circle C2 centre (-31.43, -16.9) radius 5
  concentric C1 C2
  dimension "d604" diameter C1 = 2
  dimension "d605" diameter C2 = 10
extrude "Extrude63" new body sketch "Sketch46" along normal blind 13
combine "Combine14"
extrude "Extrude64" cut sketch "Sketch46" along normal blind 12
remove_body "RemoveBody43"
extrude "Extrude65" new body sketch "Sketch46" along normal blind 13
combine "Combine15"
remove_body "RemoveBody36"
work_plane "WorkPlane13" sketch "Sketch46" AlongDistance 12
sketch "Sketch47" plane through (0, 22.5, 0) normal (0, 1, 0) x axis (1, 0, 0)
  circle C1 centre (-31.43, -16.9) radius 1
  circle C2 centre (-31.43, -16.9) radius 3
  concentric C1 C2
  dimension "d613" diameter C2 = 6
extrude "Extrude66" cut sketch "Sketch47" against normal blind 9
combine "Combine16"
combine "Combine17"
extrude "Extrude80" cut of existing geometry blind 20
sketch "Sketch49" plane through (0, 0, 19) normal (0, 0, 1) x axis (-1, 0, 0)
  line L1 (-21.9602, -12.9254) -> (-25.9602, -12.9254)
  line L2 (-21.9602, 0) -> (-21.9602, -12.9254)
  line L3 (-25.9602, 0) -> (-21.9602, 0)
  line L4 (-25.9602, -12.9254) -> (-25.9602, 0)
  line L5 (-20.8364, -17.2442) -> (-19.3192, -17.7698)
  line L6 (-18.9983, -6.3299) -> (-18.9983, -9.3299)
  line L7 (-28.12, -13.9411) -> (-26.9027, -15.0383)
  circle C1 centre (-24, -16.5) radius 1.55
  arc A1 centre (-24, -16.5) radius 3.25 clockwise from (-26.9027, -15.0383) to (-20.8364, -17.2442)
  arc A2 centre (-24, -16.5) radius 4.85 clockwise from (-19.3192, -17.7698) to (-28.12, -13.9411)
  horizontal L1
  vertical L2
  horizontal L3
  vertical L4
  dimension "d652" distance L2 L4 = 4
extrude "Extrude69" new body sketch "Sketch49" profile of L1 L2 L3 L4 along normal blind 12
extrude "Extrude70" add of existing geometry blind 7
copy_paste_bodies "CopyPasteBodies2"
combine "Combine18"
combine "Combine19"
remove_body "RemoveBody27"
combine "Combine20"
combine "Combine21"
chamfer "Chamfer9" distance 12 Rotate Angle 35
fillet "Fillet106" radius 15
fillet "Fillet107" radius 8
fillet "Fillet129" radius 4
fillet "Fillet108" radius 4.2
fillet "Fillet110" radius 1.2
fillet "Fillet111" radius 0.6
fillet "Fillet112" radius 1.3
fillet "Fillet115" radius 2
fillet "Fillet116" radius 3
fillet "Fillet117" radius 12
fillet "Fillet118" radius 15
fillet "Fillet120" radius 2
fillet "Fillet121" radius 3
fillet "Fillet123" radius 2
fillet "Fillet134" radius 2
fillet "Fillet135" radius 2
fillet "Fillet125" radius 1
fillet "Fillet127" radius 3
fillet "Fillet131" radius 1
fillet "Fillet133" radius 12
mirror "Mirror18" mirrorStitchTolerance 0.1
fillet "Fillet99" radius 5
work_plane "WorkPlane9" AlongDistance -34
sketch "Sketch44" plane through (0, -34, 0) normal (0, 1, 0) x axis (1, 0, 0)
  line L1 (-22.45, -24) -> (-25.55, -24)
  line L2 (25.55, -19) -> (22.45, -19)
  line L3 (24, -9.5) -> (-24, -9.5)
  line L4 (-8, -9.5) -> (0, -9.5)
  line L5 (-8, -14.5) -> (-8, -9.5)
  line L6 (0, -14.5) -> (-8, -14.5)
  line L7 (0, -9.5) -> (0, -14.5)
  line L8 (8, -14.5) -> (-8, -14.5)
  line L9 (8, -2) -> (8, -14.5)
  line L10 (-8, -2) -> (8, -2)
  line L11 (-8, -14.5) -> (-8, -2)
  line L12 (-27.1569, -2) -> (-0.0223, -2)
  point P8 (0, -9.5)
  point P15 (-0.0223, -2)
  parallel L2 L3
  horizontal L4
  vertical L5
  horizontal L6
  vertical L7
  midpoint L3 P8
  horizontal L8
  vertical L9
  horizontal L10
  vertical L11
  coincident L10 P15
  dimension "d572" distance L3 L12 = 7.5
  dimension "d573" distance L5 L7 = 8
  dimension "d574" distance L4 L6 = 5
  dimension "d576" distance L7 L9 = 8 (= "d573")
extrude "Extrude62" cut sketch "Sketch44" profile of L12 L4 L5 L6 L7 L8 L9 L10 L11 along normal blind 14
fillet "Fillet90" radius 2
component_insert "Component Insert7"
component_insert "Component Insert8"
joint "Assemble1" alignAngle -90 alignOffsetX 0 alignOffsetY 0 alignOffsetZ 0
joint "Assemble2" alignAngle 0 alignOffsetX 0 alignOffsetY 0 alignOffsetZ 0
joint "Assemble3" alignAngle -90 alignOffsetX 0 alignOffsetY 0 alignOffsetZ 0
joint "Assemble4" alignAngle 0 alignOffsetX 0 alignOffsetY 0 alignOffsetZ 0
joint "Assemble5" alignAngle 180 alignOffsetX 0 alignOffsetY 0 alignOffsetZ 0
component_insert "Component Insert9"
component_insert "Component Insert10"
component_insert "Component Insert11"
component_insert "Component Insert12"
component_insert "Component Insert13"
component_insert "Component Insert14"
fillet "Fillet130" radius 1.5
copy_paste "CutPaste2"
copy_paste "CutPaste3"
copy_paste "CutPaste4"
copy_paste "CutPaste5"
copy_paste "CutPaste6"
copy_paste "CutPaste7"
copy_paste "CutPaste8"
copy_paste "CutPaste9"
copy_paste "CutPaste10"
copy_paste "CutPaste11"
copy_paste "CutPaste12"
copy_paste "CutPaste13"
copy_paste "CutPaste14"
joint "Assemble8" alignAngle 0 alignOffsetX 0 alignOffsetY 0 alignOffsetZ 0
joint "Assemble9" alignAngle 0 alignOffsetX 0 alignOffsetY 0 alignOffsetZ 0
as_built_joint "As-built1"
as_built_joint "As-built2"
as_built_joint "As-built3"
as_built_joint "As-built4"
joint "Assemble10" alignAngle -50 alignOffsetX 0 alignOffsetY 0 alignOffsetZ 0
joint "Assemble11" alignAngle 40 alignOffsetX 0 alignOffsetY 0 alignOffsetZ 0
joint "Assemble12" alignAngle -50 alignOffsetX 0 alignOffsetY 0 alignOffsetZ 0
joint "Assemble13" alignAngle -40 alignOffsetX 0 alignOffsetY 0 alignOffsetZ 0
copy_paste "CutPaste16"
copy_paste_bodies "CopyPasteBodies1"
move "Move1" RotateAngle 10
component_insert "Component Insert1"
extrude "Extrude1" add of existing geometry blind -6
